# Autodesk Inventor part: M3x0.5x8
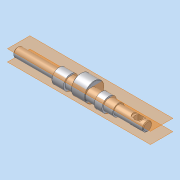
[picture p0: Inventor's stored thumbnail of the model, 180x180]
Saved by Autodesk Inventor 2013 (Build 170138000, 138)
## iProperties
Company: 한국ATC센터
Created: 2009-02
Part Number: M3x0.5x8
Document SubType Name: Modeling
Designer: KYOUNG IL JANG
Density: 7.86 g/cm^3
Mass: 246.092 g
Surface Area: 95.129 cm^2
Volume: 31.3094 cm^3
Material: 강, 연강
Vendor: CBT Solutions
Author: KYOUNG IL JANG
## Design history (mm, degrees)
sketch "스케치1"
  geometry: L1 (-84.5, 0)-(84.5, 0); L2 (-84.5, 0)-(-84.5, 6); L3 (-84.5, 6)-(-30.5, 6); L4 (-30.5, 6)-(-30.5, 9.5); L5 (-30.5, 9.5)-(-15.5, 9.5); L6 (-15.5, 9.5)-(-15.5, 7.5); L7 (-15.5, 7.5)-(46.5, 7.5); L8 (84.5, 6)-(84.5, 0); L9 (34.5, 7.5)-(34.5, 9.5); L10 (34.5, 9.5)-(24.5, 9.5); L11 (24.5, 9.5)-(24.5, 7.5); L12 (46.5, 7.5)-(46.5, 6); L13 (46.5, 6)-(84.5, 6); 2 further points
  constraints: 26 end point, 6 parallel, 6 perpendicular, 2 point on line, 1 coincident, 1 horizontal, 1 midpoint
  dimensions: "d1" = 12 diameter of L3 L1; "d2" = 15 diameter of L7 L1; "d4" = 15 distance of L4.end L5.end; "d5" = 19 diameter of L5 L1; "d24" = 10 distance of L9.end L10.end; "d25" = 19 diameter of L10 L1; "d27" = 40 distance between parallel lines of L11 L6; "d28" = 54 distance of L2.end L3.end; "d29" = 50 distance between parallel lines of L8 L9; "d41" = 38 distance between parallel lines of L8 L12; "d42" = 12 diameter of L13 L1
revolve "회전1" stored, may be unused: angle "d6" = 90 deg
node "작업 평면1"
sketch "스케치2"
  geometry: C1 r 7.5 at (0, 0) reference; C2 r 12.5 at (0, 4.5); 1 further point
  constraints: 1 centre point, 1 vertical alignment
  dimensions: "d8" = 4.5 distance of point (0, 0) C2.centre; "d9" = 25 diameter of C2
extrude "돌출1" join sketch "스케치2" distance "d10" = 18; taper "d11" = 0 deg
chamfer "모따기1" distance "d12" = 1; stored, may be unused: second distance "d13" = 2, angle "d14" = 45 deg
chamfer "모따기2" distance "d15" = 0.5; stored, may be unused: second distance "d16" = 2, angle "d17" = 45 deg
node "작업 평면2"
sketch "스케치3"
  geometry: L1 (4, -2)-(18, -2); L2 (18, 2)-(4, 2); L3 (27, 5)-(27, -5) reference; A1 r 2 centre (18, 0) between (18, -2) and (18, 2); A2 r 2 centre (4, 0) between (4, 2) and (4, -2); 2 further points
  constraints: 4 end point, 4 point on circle, 4 tangent, 2 centre point, 1 horizontal, 1 horizontal alignment, 1 midpoint, 1 parallel
  dimensions: "d18" = 7 distance edge to line of A1 L3; "d19" = 4 distance between parallel lines of L2 L1; "d20" = 18 dimension on A1 A2
extrude "돌출2" cut sketch "스케치3" distance "d21" = 2.5; taper "d22" = 0 deg
revolve "회전2" stored, may be unused: angle "d26" = 90 deg
node "작업 평면3"
sketch "스케치4"
  geometry: L1 (44, 5)-(44, -5) reference; 2 further points
  constraints: 1 horizontal alignment
  dimensions: "d30" = 12 distance from line of point (32, 0) L1
hole "구멍1" sketch "스케치4" at (32, 0) diameter "d31" = 9; stored, may be unused: countersink angle "d35" = 90 deg, drill point angle "d37" = 118 deg; dims "d32" = 6, "d33" = 14, "d34" = 3, "d36" = 8
node "작업 평면4"
sketch "스케치5"
  geometry: C1 r 8 at (32, 0); A1 r 4.5 centre (32, 0) between (29.879, 3.969) and (29.879, -3.969) reference; A2 r 4.5 centre (32, 0) between (34.121, -3.969) and (34.121, 3.969) reference; 1 further point
  constraints: 2 horizontal alignment, 1 centre point, 1 coincident
  dimensions: "d38" = 16 diameter of C1
extrude "돌출3" cut sketch "스케치5" distance "d39" = 3; taper "d40" = 0 deg
node "솔리드1"
node "투영된 루프1"
other parameters: "d7" = 8.5
